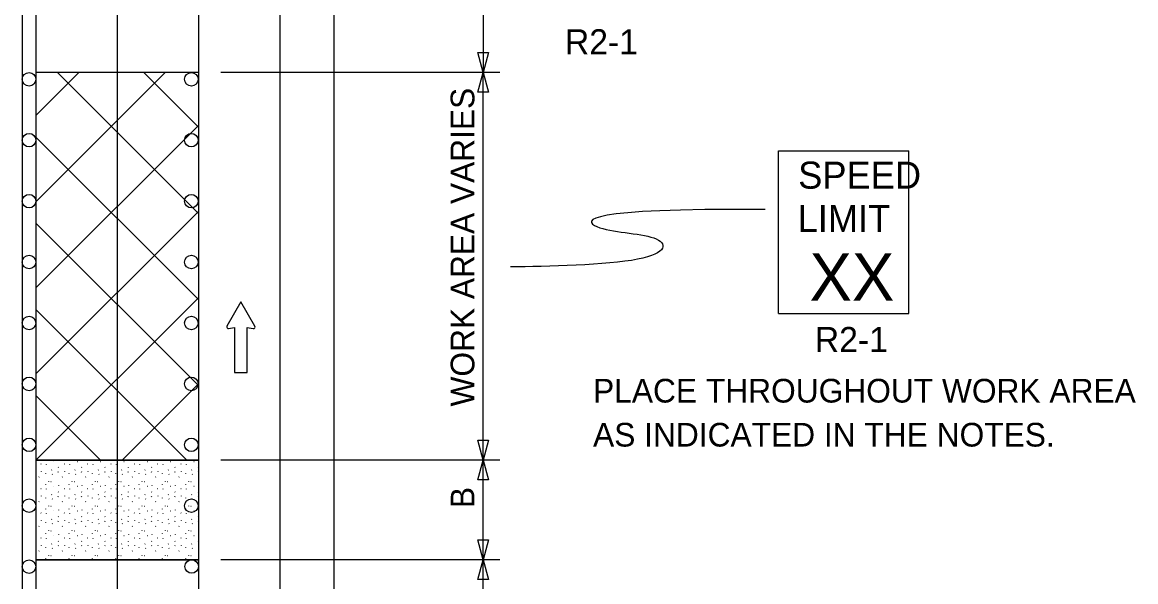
# Model space of a CAD drawing. Extents: x 16751 to 18475, y 5726 to 6923.
# Drawn here: x 17076.1 to 17404.7, y 6573.1 to 6738.4 of the extents above; entities that cross this region are included whole.
import ezdxf

# ---------------------------------------------------------------- set-up
doc = ezdxf.new("R2010")
doc.units = 0
for name, color, linetype in [('ALI_LEGAL_EX', 7, 'Continuous'), ('MT_SCRATCH_LEVEL_A', 7, 'Continuous'), ('MT_SCRATCH_LEVEL_E', 7, 'Continuous'), ('PAVT_EDGE_EX', 7, 'Continuous'), ('TRAFFIC_SIGNS_PR', 7, 'Continuous'), ('TYPICAL_TEXT_DIMEN_PR', 7, 'Continuous')]:
    doc.layers.add(name, color=color, linetype=linetype)

msp = doc.modelspace()

# ---------------------------------------------------------------- linework, layer by layer
at = {"layer": 'ALI_LEGAL_EX'}
for p, q in [((17104.08, 6911.72), (17104.08, 6082.53)), ((17128.08, 6911.72), (17128.08, 6082.53)), ((17128.08, 6911.72), (17128.08, 6082.53))]:
    msp.add_line(p, q, dxfattribs=at)
for points in [[(17104.08, 6711.72), (17104.08, 6686.72)], [(17128.08, 6711.72), (17128.08, 6686.72)], [(17104.08, 6611.72), (17104.08, 6586.72)], [(17128.08, 6611.72), (17128.08, 6586.72)]]:
    msp.add_lwpolyline(points, dxfattribs=at)
at = {"layer": 'MT_SCRATCH_LEVEL_A'}
for p, q in [((17128.08, 6723.53), (17080.08, 6723.53)), ((17128.08, 6608.99), (17080.08, 6608.99)), ((17128.08, 6579.57), (17080.08, 6579.57))]:
    msp.add_line(p, q, dxfattribs=at)
at = {"layer": 'MT_SCRATCH_LEVEL_E'}
for p, q in [((17140.6, 6655.79), (17136.49, 6648.55)), ((17140.6, 6655.79), (17136.49, 6648.55)), ((17144.75, 6648.55), (17140.6, 6655.79)), ((17144.75, 6648.55), (17140.6, 6655.79)), ((17136.97, 6647.87), (17138.75, 6648.18)), ((17136.97, 6647.87), (17138.75, 6648.18)), ((17138.75, 6648.18), (17138.75, 6634.93)), ((17138.75, 6648.18), (17138.75, 6634.93)), ((17142.49, 6634.93), (17142.49, 6648.18)), ((17142.49, 6648.18), (17144.27, 6647.87)), ((17142.49, 6634.93), (17142.49, 6648.18)), ((17142.49, 6648.18), (17144.27, 6647.87)), ((17138.75, 6634.93), (17142.49, 6634.93)), ((17138.75, 6634.93), (17142.49, 6634.93))]:
    msp.add_line(p, q, dxfattribs=at)
for centre, start, end in [((17136.9, 6648.33), 150.4248, 279.9638), ((17136.9, 6648.33), 150.4248, 279.9638), ((17144.34, 6648.33), 260.0362, 29.7731), ((17144.34, 6648.33), 260.0362, 29.7731)]:
    msp.add_arc(centre, 0.463, start, end, dxfattribs=at)
at = {"layer": 'PAVT_EDGE_EX'}
for p, q in [((17076.08, 6911.72), (17076.08, 6082.53)), ((17080.08, 6911.72), (17080.08, 6082.53)), ((17152.08, 6911.72), (17152.08, 6082.53)), ((17168.08, 6911.72), (17168.08, 6082.53)), ((17128.08, 6723.53), (17080.08, 6723.53)), ((17080.08, 6723.53), (17080.08, 6608.99)), ((17080.08, 6710.82), (17092.79, 6723.53)), ((17080.08, 6685.36), (17118.24, 6723.53)), ((17128.08, 6681.91), (17086.45, 6723.53)), ((17128.08, 6707.37), (17111.91, 6723.53)), ((17080.08, 6659.91), (17128.08, 6707.91)), ((17128.08, 6656.45), (17080.08, 6704.45)), ((17080.08, 6634.45), (17128.08, 6682.45)), ((17128.08, 6631), (17080.08, 6679)), ((17080.08, 6608.99), (17128.08, 6656.99)), ((17124.62, 6608.99), (17080.08, 6653.54)), ((17105.53, 6608.99), (17128.08, 6631.54)), ((17099.17, 6608.99), (17080.08, 6628.09)), ((17080.08, 6608.99), (17128.08, 6608.99)), ((17128.08, 6608.99), (17080.08, 6608.99)), ((17080.08, 6608.99), (17080.08, 6579.57)), ((17080.08, 6608.99), (17080.08, 6608.99)), ((17081.57, 6607.94), (17081.62, 6607.87)), ((17083.1, 6607.81), (17083.15, 6607.73)), ((17084.74, 6606.02), (17084.8, 6606.13)), ((17085.39, 6608.62), (17085.44, 6608.55)), ((17086.67, 6606.89), (17086.72, 6606.81)), ((17086.84, 6608.77), (17086.89, 6608.89)), ((17088.46, 6607.94), (17088.51, 6607.87)), ((17089.99, 6607.81), (17090.04, 6607.73)), ((17091.63, 6606.02), (17091.68, 6606.13)), ((17092.28, 6608.62), (17092.33, 6608.55)), ((17093.56, 6606.89), (17093.61, 6606.81)), ((17093.73, 6608.77), (17093.78, 6608.89)), ((17095.35, 6607.94), (17095.4, 6607.87)), ((17096.88, 6607.81), (17096.93, 6607.73)), ((17098.52, 6606.02), (17098.57, 6606.13)), ((17099.17, 6608.62), (17099.22, 6608.55)), ((17100.44, 6606.89), (17100.5, 6606.81)), ((17100.62, 6608.77), (17100.67, 6608.89)), ((17102.24, 6607.94), (17102.29, 6607.87)), ((17103.76, 6607.81), (17103.82, 6607.73)), ((17105.41, 6606.02), (17105.46, 6606.13)), ((17106.05, 6608.62), (17106.11, 6608.55)), ((17107.33, 6606.89), (17107.38, 6606.81)), ((17107.5, 6608.77), (17107.56, 6608.89)), ((17109.12, 6607.94), (17109.17, 6607.87)), ((17110.65, 6607.81), (17110.7, 6607.73)), ((17112.29, 6606.02), (17112.35, 6606.13)), ((17112.94, 6608.62), (17112.99, 6608.55)), ((17114.22, 6606.89), (17114.27, 6606.81)), ((17114.39, 6608.77), (17114.44, 6608.89)), ((17116.01, 6607.94), (17116.06, 6607.87)), ((17117.54, 6607.81), (17117.59, 6607.73)), ((17119.18, 6606.02), (17119.23, 6606.13)), ((17119.83, 6608.62), (17119.88, 6608.55)), ((17121.11, 6606.89), (17121.16, 6606.81)), ((17121.28, 6608.77), (17121.33, 6608.89)), ((17122.9, 6607.94), (17122.95, 6607.87)), ((17124.43, 6607.81), (17124.48, 6607.73)), ((17126.07, 6606.02), (17126.12, 6606.13)), ((17126.72, 6608.62), (17126.77, 6608.55)), ((17127.99, 6606.89), (17128.05, 6606.81)), ((17081, 6603.98), (17081.05, 6604.1)), ((17081.62, 6605.74), (17081.67, 6605.66)), ((17082.9, 6605.16), (17082.92, 6605.04)), ((17083.79, 6602.75), (17083.84, 6602.67)), ((17084.52, 6602.72), (17084.58, 6602.64)), ((17084.93, 6604.82), (17084.98, 6604.74)), ((17086.71, 6605.49), (17086.76, 6605.6)), ((17087.89, 6603.98), (17087.94, 6604.1)), ((17088.51, 6605.74), (17088.56, 6605.66)), ((17089.79, 6605.16), (17089.8, 6605.04)), ((17090.67, 6602.75), (17090.72, 6602.67)), ((17091.41, 6602.72), (17091.46, 6602.64)), ((17091.82, 6604.82), (17091.87, 6604.74)), ((17093.6, 6605.49), (17093.65, 6605.6)), ((17094.78, 6603.98), (17094.83, 6604.1)), ((17095.4, 6605.74), (17095.45, 6605.66)), ((17096.68, 6605.16), (17096.69, 6605.04)), ((17097.56, 6602.75), (17097.61, 6602.67)), ((17098.3, 6602.72), (17098.35, 6602.64)), ((17098.71, 6604.82), (17098.76, 6604.74)), ((17100.49, 6605.49), (17100.54, 6605.6)), ((17101.67, 6603.98), (17101.72, 6604.1)), ((17102.28, 6605.74), (17102.33, 6605.66)), ((17103.56, 6605.16), (17103.58, 6605.04)), ((17104.45, 6602.75), (17104.5, 6602.67)), ((17105.19, 6602.72), (17105.24, 6602.64)), ((17105.6, 6604.82), (17105.65, 6604.74)), ((17107.37, 6605.49), (17107.43, 6605.6)), ((17108.55, 6603.98), (17108.6, 6604.1)), ((17109.17, 6605.74), (17109.22, 6605.66)), ((17110.45, 6605.16), (17110.47, 6605.04)), ((17111.34, 6602.75), (17111.39, 6602.67)), ((17112.07, 6602.72), (17112.12, 6602.64)), ((17112.48, 6604.82), (17112.53, 6604.74)), ((17114.26, 6605.49), (17114.31, 6605.6)), ((17115.44, 6603.98), (17115.49, 6604.1)), ((17116.06, 6605.74), (17116.11, 6605.66)), ((17117.34, 6605.16), (17117.35, 6605.04)), ((17118.22, 6602.75), (17118.28, 6602.67)), ((17118.96, 6602.72), (17119.01, 6602.64)), ((17119.37, 6604.82), (17119.42, 6604.74)), ((17121.15, 6605.49), (17121.2, 6605.6)), ((17122.33, 6603.98), (17122.38, 6604.1)), ((17122.95, 6605.74), (17123, 6605.66)), ((17124.23, 6605.16), (17124.24, 6605.04)), ((17125.11, 6602.75), (17125.16, 6602.67)), ((17125.85, 6602.72), (17125.9, 6602.64)), ((17126.26, 6604.82), (17126.31, 6604.74)), ((17128.04, 6605.49), (17128.08, 6605.57)), ((17081.57, 6600.66), (17081.62, 6600.58)), ((17083.02, 6601.79), (17083.07, 6601.9)), ((17083.1, 6600.52), (17083.15, 6600.44)), ((17085.39, 6601.34), (17085.44, 6601.26)), ((17086.67, 6599.6), (17086.72, 6599.52)), ((17086.84, 6601.49), (17086.89, 6601.61)), ((17088.46, 6600.66), (17088.51, 6600.58)), ((17089.91, 6601.79), (17089.96, 6601.9)), ((17089.99, 6600.52), (17090.04, 6600.44)), ((17092.28, 6601.34), (17092.33, 6601.26)), ((17093.56, 6599.6), (17093.61, 6599.52)), ((17093.73, 6601.49), (17093.78, 6601.61)), ((17095.35, 6600.66), (17095.4, 6600.58)), ((17096.8, 6601.79), (17096.85, 6601.9)), ((17096.88, 6600.52), (17096.93, 6600.44)), ((17099.17, 6601.34), (17099.22, 6601.26)), ((17100.44, 6599.6), (17100.5, 6599.52)), ((17100.62, 6601.49), (17100.67, 6601.61)), ((17102.24, 6600.66), (17102.29, 6600.58)), ((17103.69, 6601.79), (17103.74, 6601.9)), ((17103.76, 6600.52), (17103.82, 6600.44)), ((17106.05, 6601.34), (17106.11, 6601.26)), ((17107.33, 6599.6), (17107.38, 6599.52)), ((17107.5, 6601.49), (17107.56, 6601.61)), ((17109.12, 6600.66), (17109.17, 6600.58)), ((17110.57, 6601.79), (17110.62, 6601.9)), ((17110.65, 6600.52), (17110.7, 6600.44)), ((17112.94, 6601.34), (17112.99, 6601.26)), ((17114.22, 6599.6), (17114.27, 6599.52)), ((17114.39, 6601.49), (17114.44, 6601.61)), ((17116.01, 6600.66), (17116.06, 6600.58)), ((17117.46, 6601.79), (17117.51, 6601.9)), ((17117.54, 6600.52), (17117.59, 6600.44)), ((17119.83, 6601.34), (17119.88, 6601.26)), ((17121.11, 6599.6), (17121.16, 6599.52)), ((17121.28, 6601.49), (17121.33, 6601.61)), ((17122.9, 6600.66), (17122.95, 6600.58)), ((17124.35, 6601.79), (17124.4, 6601.9)), ((17124.43, 6600.52), (17124.48, 6600.44)), ((17126.72, 6601.34), (17126.77, 6601.26)), ((17127.99, 6599.6), (17128.05, 6599.52)), ((17081, 6596.7), (17081.05, 6596.82)), ((17081.62, 6598.45), (17081.67, 6598.37)), ((17082.9, 6597.88), (17082.92, 6597.76)), ((17084.74, 6598.73), (17084.8, 6598.85)), ((17084.93, 6597.53), (17084.98, 6597.45)), ((17086.71, 6598.2), (17086.76, 6598.32)), ((17087.89, 6596.7), (17087.94, 6596.82)), ((17088.51, 6598.45), (17088.56, 6598.37)), ((17089.79, 6597.88), (17089.8, 6597.76)), ((17091.63, 6598.73), (17091.68, 6598.85)), ((17091.82, 6597.53), (17091.87, 6597.45)), ((17093.6, 6598.2), (17093.65, 6598.32)), ((17094.78, 6596.7), (17094.83, 6596.82)), ((17095.4, 6598.45), (17095.45, 6598.37)), ((17096.68, 6597.88), (17096.69, 6597.76)), ((17098.52, 6598.73), (17098.57, 6598.85)), ((17098.71, 6597.53), (17098.76, 6597.45)), ((17100.49, 6598.2), (17100.54, 6598.32)), ((17101.67, 6596.7), (17101.72, 6596.82)), ((17102.28, 6598.45), (17102.33, 6598.37)), ((17103.56, 6597.88), (17103.58, 6597.76)), ((17105.41, 6598.73), (17105.46, 6598.85)), ((17105.6, 6597.53), (17105.65, 6597.45)), ((17107.37, 6598.2), (17107.43, 6598.32)), ((17108.55, 6596.7), (17108.6, 6596.82)), ((17109.17, 6598.45), (17109.22, 6598.37)), ((17110.45, 6597.88), (17110.47, 6597.76)), ((17112.29, 6598.73), (17112.35, 6598.85)), ((17112.48, 6597.53), (17112.53, 6597.45)), ((17114.26, 6598.2), (17114.31, 6598.32)), ((17115.44, 6596.7), (17115.49, 6596.82)), ((17116.06, 6598.45), (17116.11, 6598.37)), ((17117.34, 6597.88), (17117.35, 6597.76)), ((17119.18, 6598.73), (17119.23, 6598.85)), ((17119.37, 6597.53), (17119.42, 6597.45)), ((17121.15, 6598.2), (17121.2, 6598.32)), ((17122.33, 6596.7), (17122.38, 6596.82)), ((17122.95, 6598.45), (17123, 6598.37)), ((17124.23, 6597.88), (17124.24, 6597.76)), ((17126.07, 6598.73), (17126.12, 6598.85)), ((17126.26, 6597.53), (17126.31, 6597.45)), ((17128.04, 6598.2), (17128.08, 6598.29)), ((17081.57, 6593.38), (17081.62, 6593.3)), ((17083.02, 6594.5), (17083.07, 6594.62)), ((17083.1, 6593.24), (17083.15, 6593.16)), ((17083.79, 6595.46), (17083.84, 6595.38)), ((17084.52, 6595.43), (17084.58, 6595.35)), ((17085.39, 6594.05), (17085.44, 6593.98)), ((17086.84, 6594.2), (17086.89, 6594.32)), ((17088.46, 6593.38), (17088.51, 6593.3)), ((17089.91, 6594.5), (17089.96, 6594.62)), ((17089.99, 6593.24), (17090.04, 6593.16)), ((17090.67, 6595.46), (17090.72, 6595.38)), ((17091.41, 6595.43), (17091.46, 6595.35)), ((17092.28, 6594.05), (17092.33, 6593.98)), ((17093.73, 6594.2), (17093.78, 6594.32)), ((17095.35, 6593.38), (17095.4, 6593.3)), ((17096.8, 6594.5), (17096.85, 6594.62)), ((17096.88, 6593.24), (17096.93, 6593.16)), ((17097.56, 6595.46), (17097.61, 6595.38)), ((17098.3, 6595.43), (17098.35, 6595.35)), ((17099.17, 6594.05), (17099.22, 6593.98)), ((17100.62, 6594.2), (17100.67, 6594.32)), ((17102.24, 6593.38), (17102.29, 6593.3)), ((17103.69, 6594.5), (17103.74, 6594.62)), ((17103.76, 6593.24), (17103.82, 6593.16)), ((17104.45, 6595.46), (17104.5, 6595.38)), ((17105.19, 6595.43), (17105.24, 6595.35)), ((17106.05, 6594.05), (17106.11, 6593.98)), ((17107.5, 6594.2), (17107.56, 6594.32)), ((17109.12, 6593.38), (17109.17, 6593.3)), ((17110.57, 6594.5), (17110.62, 6594.62)), ((17110.65, 6593.24), (17110.7, 6593.16)), ((17111.34, 6595.46), (17111.39, 6595.38)), ((17112.07, 6595.43), (17112.12, 6595.35)), ((17112.94, 6594.05), (17112.99, 6593.98)), ((17114.39, 6594.2), (17114.44, 6594.32)), ((17116.01, 6593.38), (17116.06, 6593.3)), ((17117.46, 6594.5), (17117.51, 6594.62)), ((17117.54, 6593.24), (17117.59, 6593.16)), ((17118.22, 6595.46), (17118.28, 6595.38)), ((17118.96, 6595.43), (17119.01, 6595.35)), ((17119.83, 6594.05), (17119.88, 6593.98)), ((17121.28, 6594.2), (17121.33, 6594.32)), ((17122.9, 6593.38), (17122.95, 6593.3)), ((17124.35, 6594.5), (17124.4, 6594.62)), ((17124.43, 6593.24), (17124.48, 6593.16)), ((17125.11, 6595.46), (17125.16, 6595.38)), ((17125.85, 6595.43), (17125.9, 6595.35)), ((17126.72, 6594.05), (17126.77, 6593.98)), ((17081, 6589.41), (17081.05, 6589.53)), ((17081.62, 6591.17), (17081.67, 6591.09)), ((17082.9, 6590.59), (17082.92, 6590.47)), ((17084.74, 6591.45), (17084.8, 6591.56)), ((17084.93, 6590.25), (17084.98, 6590.17)), ((17086.67, 6592.32), (17086.72, 6592.24)), ((17086.71, 6590.91), (17086.76, 6591.03)), ((17087.89, 6589.41), (17087.94, 6589.53)), ((17088.51, 6591.17), (17088.56, 6591.09)), ((17089.79, 6590.59), (17089.8, 6590.47)), ((17091.63, 6591.45), (17091.68, 6591.56)), ((17091.82, 6590.25), (17091.87, 6590.17)), ((17093.56, 6592.32), (17093.61, 6592.24)), ((17093.6, 6590.91), (17093.65, 6591.03)), ((17094.78, 6589.41), (17094.83, 6589.53)), ((17095.4, 6591.17), (17095.45, 6591.09)), ((17096.68, 6590.59), (17096.69, 6590.47)), ((17098.52, 6591.45), (17098.57, 6591.56)), ((17098.71, 6590.25), (17098.76, 6590.17)), ((17100.44, 6592.32), (17100.5, 6592.24)), ((17100.49, 6590.91), (17100.54, 6591.03)), ((17101.67, 6589.41), (17101.72, 6589.53)), ((17102.28, 6591.17), (17102.33, 6591.09)), ((17103.56, 6590.59), (17103.58, 6590.47)), ((17105.41, 6591.45), (17105.46, 6591.56)), ((17105.6, 6590.25), (17105.65, 6590.17)), ((17107.33, 6592.32), (17107.38, 6592.24)), ((17107.37, 6590.91), (17107.43, 6591.03)), ((17108.55, 6589.41), (17108.6, 6589.53)), ((17109.17, 6591.17), (17109.22, 6591.09)), ((17110.45, 6590.59), (17110.47, 6590.47)), ((17112.29, 6591.45), (17112.35, 6591.56)), ((17112.48, 6590.25), (17112.53, 6590.17)), ((17114.22, 6592.32), (17114.27, 6592.24)), ((17114.26, 6590.91), (17114.31, 6591.03)), ((17115.44, 6589.41), (17115.49, 6589.53)), ((17116.06, 6591.17), (17116.11, 6591.09)), ((17117.34, 6590.59), (17117.35, 6590.47)), ((17119.18, 6591.45), (17119.23, 6591.56)), ((17119.37, 6590.25), (17119.42, 6590.17)), ((17121.11, 6592.32), (17121.16, 6592.24)), ((17121.15, 6590.91), (17121.2, 6591.03)), ((17122.33, 6589.41), (17122.38, 6589.53)), ((17122.95, 6591.17), (17123, 6591.09)), ((17124.23, 6590.59), (17124.24, 6590.47)), ((17126.07, 6591.45), (17126.12, 6591.56)), ((17126.26, 6590.25), (17126.31, 6590.17)), ((17127.99, 6592.32), (17128.05, 6592.24)), ((17128.04, 6590.91), (17128.08, 6591)), ((17081.57, 6586.09), (17081.62, 6586.01)), ((17083.02, 6587.22), (17083.07, 6587.33)), ((17083.79, 6588.18), (17083.84, 6588.1)), ((17084.52, 6588.15), (17084.58, 6588.07)), ((17085.39, 6586.77), (17085.44, 6586.69)), ((17086.84, 6586.92), (17086.89, 6587.04)), ((17088.46, 6586.09), (17088.51, 6586.01)), ((17089.91, 6587.22), (17089.96, 6587.33)), ((17090.67, 6588.18), (17090.72, 6588.1)), ((17091.41, 6588.15), (17091.46, 6588.07)), ((17092.28, 6586.77), (17092.33, 6586.69)), ((17093.73, 6586.92), (17093.78, 6587.04)), ((17095.35, 6586.09), (17095.4, 6586.01)), ((17096.8, 6587.22), (17096.85, 6587.33)), ((17097.56, 6588.18), (17097.61, 6588.1)), ((17098.3, 6588.15), (17098.35, 6588.07)), ((17099.17, 6586.77), (17099.22, 6586.69)), ((17100.62, 6586.92), (17100.67, 6587.04)), ((17102.24, 6586.09), (17102.29, 6586.01)), ((17103.69, 6587.22), (17103.74, 6587.33)), ((17104.45, 6588.18), (17104.5, 6588.1)), ((17105.19, 6588.15), (17105.24, 6588.07)), ((17106.05, 6586.77), (17106.11, 6586.69)), ((17107.5, 6586.92), (17107.56, 6587.04)), ((17109.12, 6586.09), (17109.17, 6586.01)), ((17110.57, 6587.22), (17110.62, 6587.33)), ((17111.34, 6588.18), (17111.39, 6588.1)), ((17112.07, 6588.15), (17112.12, 6588.07)), ((17112.94, 6586.77), (17112.99, 6586.69)), ((17114.39, 6586.92), (17114.44, 6587.04)), ((17116.01, 6586.09), (17116.06, 6586.01)), ((17117.46, 6587.22), (17117.51, 6587.33)), ((17118.22, 6588.18), (17118.28, 6588.1)), ((17118.96, 6588.15), (17119.01, 6588.07)), ((17119.83, 6586.77), (17119.88, 6586.69)), ((17121.28, 6586.92), (17121.33, 6587.04)), ((17122.9, 6586.09), (17122.95, 6586.01)), ((17124.35, 6587.22), (17124.4, 6587.33)), ((17125.11, 6588.18), (17125.16, 6588.1)), ((17125.85, 6588.15), (17125.9, 6588.07)), ((17126.72, 6586.77), (17126.77, 6586.69)), ((17081.62, 6583.88), (17081.67, 6583.8)), ((17082.9, 6583.31), (17082.92, 6583.19)), ((17083.1, 6585.95), (17083.15, 6585.87)), ((17084.74, 6584.16), (17084.8, 6584.28)), ((17084.93, 6582.96), (17084.98, 6582.88)), ((17086.67, 6585.03), (17086.72, 6584.95)), ((17086.71, 6583.63), (17086.76, 6583.75)), ((17088.51, 6583.88), (17088.56, 6583.8)), ((17089.79, 6583.31), (17089.8, 6583.19)), ((17089.99, 6585.95), (17090.04, 6585.87)), ((17091.63, 6584.16), (17091.68, 6584.28)), ((17091.82, 6582.96), (17091.87, 6582.88)), ((17093.56, 6585.03), (17093.61, 6584.95)), ((17093.6, 6583.63), (17093.65, 6583.75)), ((17095.4, 6583.88), (17095.45, 6583.8)), ((17096.68, 6583.31), (17096.69, 6583.19)), ((17096.88, 6585.95), (17096.93, 6585.87)), ((17098.52, 6584.16), (17098.57, 6584.28)), ((17098.71, 6582.96), (17098.76, 6582.88)), ((17100.44, 6585.03), (17100.5, 6584.95)), ((17100.49, 6583.63), (17100.54, 6583.75)), ((17102.28, 6583.88), (17102.33, 6583.8)), ((17103.56, 6583.31), (17103.58, 6583.19)), ((17103.76, 6585.95), (17103.82, 6585.87)), ((17105.41, 6584.16), (17105.46, 6584.28)), ((17105.6, 6582.96), (17105.65, 6582.88)), ((17107.33, 6585.03), (17107.38, 6584.95)), ((17107.37, 6583.63), (17107.43, 6583.75)), ((17109.17, 6583.88), (17109.22, 6583.8)), ((17110.45, 6583.31), (17110.47, 6583.19)), ((17110.65, 6585.95), (17110.7, 6585.87)), ((17112.29, 6584.16), (17112.35, 6584.28)), ((17112.48, 6582.96), (17112.53, 6582.88)), ((17114.22, 6585.03), (17114.27, 6584.95)), ((17114.26, 6583.63), (17114.31, 6583.75)), ((17116.06, 6583.88), (17116.11, 6583.8)), ((17117.34, 6583.31), (17117.35, 6583.19)), ((17117.54, 6585.95), (17117.59, 6585.87)), ((17119.18, 6584.16), (17119.23, 6584.28)), ((17119.37, 6582.96), (17119.42, 6582.88)), ((17121.11, 6585.03), (17121.16, 6584.95)), ((17121.15, 6583.63), (17121.2, 6583.75)), ((17122.95, 6583.88), (17123, 6583.8)), ((17124.23, 6583.31), (17124.24, 6583.19)), ((17124.43, 6585.95), (17124.48, 6585.87)), ((17126.07, 6584.16), (17126.12, 6584.28)), ((17126.26, 6582.96), (17126.31, 6582.88)), ((17127.99, 6585.03), (17128.05, 6584.95)), ((17128.04, 6583.63), (17128.08, 6583.72)), ((17080.08, 6579.57), (17128.08, 6579.57)), ((17081, 6582.13), (17081.05, 6582.24)), ((17083.02, 6579.93), (17083.07, 6580.05)), ((17083.79, 6580.89), (17083.84, 6580.81)), ((17084.52, 6580.86), (17084.58, 6580.78)), ((17086.84, 6579.63), (17086.89, 6579.75)), ((17087.89, 6582.13), (17087.94, 6582.24)), ((17089.91, 6579.93), (17089.96, 6580.05)), ((17090.67, 6580.89), (17090.72, 6580.81)), ((17091.41, 6580.86), (17091.46, 6580.78)), ((17093.73, 6579.63), (17093.78, 6579.75)), ((17094.78, 6582.13), (17094.83, 6582.24)), ((17096.8, 6579.93), (17096.85, 6580.05)), ((17097.56, 6580.89), (17097.61, 6580.81)), ((17098.3, 6580.86), (17098.35, 6580.78)), ((17100.62, 6579.63), (17100.67, 6579.75)), ((17101.67, 6582.13), (17101.72, 6582.24)), ((17103.69, 6579.93), (17103.74, 6580.05)), ((17104.45, 6580.89), (17104.5, 6580.81)), ((17105.19, 6580.86), (17105.24, 6580.78)), ((17107.5, 6579.63), (17107.56, 6579.75)), ((17108.55, 6582.13), (17108.6, 6582.24)), ((17110.57, 6579.93), (17110.62, 6580.05)), ((17111.34, 6580.89), (17111.39, 6580.81)), ((17112.07, 6580.86), (17112.12, 6580.78)), ((17114.39, 6579.63), (17114.44, 6579.75)), ((17115.44, 6582.13), (17115.49, 6582.24)), ((17117.46, 6579.93), (17117.51, 6580.05)), ((17118.22, 6580.89), (17118.28, 6580.81)), ((17118.96, 6580.86), (17119.01, 6580.78)), ((17121.28, 6579.63), (17121.33, 6579.75)), ((17122.33, 6582.13), (17122.38, 6582.24)), ((17124.35, 6579.93), (17124.4, 6580.05)), ((17125.11, 6580.89), (17125.16, 6580.81)), ((17125.85, 6580.86), (17125.9, 6580.78))]:
    msp.add_line(p, q, dxfattribs=at)
at = {"layer": 'TRAFFIC_SIGNS_PR'}
for p, q in [((17299.32, 6700.34), (17337.72, 6700.34)), ((17299.32, 6652.34), (17299.32, 6700.34)), ((17337.72, 6652.34), (17337.72, 6700.34)), ((17299.32, 6652.34), (17337.72, 6652.34))]:
    msp.add_line(p, q, dxfattribs=at)
for centre in [(17078.08, 6721.52), (17125.98, 6721.52), (17078.08, 6703.52), (17125.98, 6703.52), (17078.08, 6685.52), (17125.98, 6685.52), (17078.08, 6667.52), (17125.98, 6667.52), (17078.08, 6649.52), (17125.98, 6649.52), (17078.08, 6631.52), (17125.98, 6631.52), (17078.08, 6613.52), (17125.98, 6613.52), (17078.08, 6595.52), (17125.98, 6595.52), (17078.08, 6577.52), (17126.07, 6577.57)]:
    msp.add_circle(centre, 2, dxfattribs=at)
at = {"layer": 'TYPICAL_TEXT_DIMEN_PR'}
for p, q in [((17212.08, 6773.53), (17212.08, 6723.53)), ((17212.08, 6723.53), (17210.51, 6729.39)), ((17210.51, 6729.39), (17212.08, 6729.39)), ((17212.08, 6729.39), (17213.65, 6729.39)), ((17213.65, 6729.39), (17212.08, 6723.53)), ((17217.08, 6723.53), (17134.68, 6723.53)), ((17210.51, 6717.67), (17212.08, 6723.53)), ((17212.08, 6608.99), (17212.08, 6723.53)), ((17212.08, 6723.53), (17213.65, 6717.67)), ((17212.08, 6717.67), (17210.51, 6717.67)), ((17213.65, 6717.67), (17212.08, 6717.67)), ((17212.08, 6608.99), (17210.51, 6614.86)), ((17210.51, 6614.86), (17212.08, 6614.86)), ((17212.08, 6614.86), (17213.65, 6614.86)), ((17213.65, 6614.86), (17212.08, 6608.99)), ((17217.08, 6608.99), (17134.68, 6608.99)), ((17210.51, 6603.13), (17212.08, 6608.99)), ((17212.08, 6579.57), (17212.08, 6608.99)), ((17212.08, 6608.99), (17213.65, 6603.13)), ((17212.08, 6603.13), (17210.51, 6603.13)), ((17213.65, 6603.13), (17212.08, 6603.13)), ((17212.08, 6579.57), (17210.51, 6585.43)), ((17210.51, 6585.43), (17212.08, 6585.43)), ((17212.08, 6585.43), (17213.65, 6585.43)), ((17213.65, 6585.43), (17212.08, 6579.57)), ((17217.08, 6579.57), (17134.68, 6579.57)), ((17210.51, 6573.7), (17212.08, 6579.57)), ((17212.08, 6549), (17212.08, 6579.57)), ((17212.08, 6579.57), (17213.65, 6573.7)), ((17212.08, 6573.7), (17210.51, 6573.7)), ((17213.65, 6573.7), (17212.08, 6573.7))]:
    msp.add_line(p, q, dxfattribs=at)
msp.add_open_spline([(17295.35, 6683.03), (17241.47, 6683.44), (17241.47, 6676.17), (17266.65, 6676.17), (17266.65, 6667.06), (17230.74, 6666.11), (17220.22, 6666.13)], degree=3, dxfattribs=at)

# ---------------------------------------------------------------- texts
at = {"layer": 'TRAFFIC_SIGNS_PR'}
for s, height, p in [('R2-1', 7.44, (17236.24, 6728.87)), ('SPEED', 8, (17305.09, 6689.2)), ('LIMIT', 8, (17304.93, 6676.4)), ('XX', 14.031, (17308.44, 6656.1)), ('R2-1', 7.44, (17310, 6640.9)), ('PLACE THROUGHOUT WORK AREA', 7, (17244.55, 6626.01)), ('AS INDICATED IN THE NOTES.', 7, (17244.55, 6613.01))]:
    msp.add_text(s, height=height, dxfattribs=at).set_placement(p)
at = {"layer": 'TYPICAL_TEXT_DIMEN_PR'}
for s, p in [('WORK AREA VARIES', (17209.52, 6624.85)), ('B', (17209.52, 6594.83))]:
    msp.add_text(s, height=7, rotation=90, dxfattribs=at).set_placement(p)

doc.saveas('drawing.dxf')
